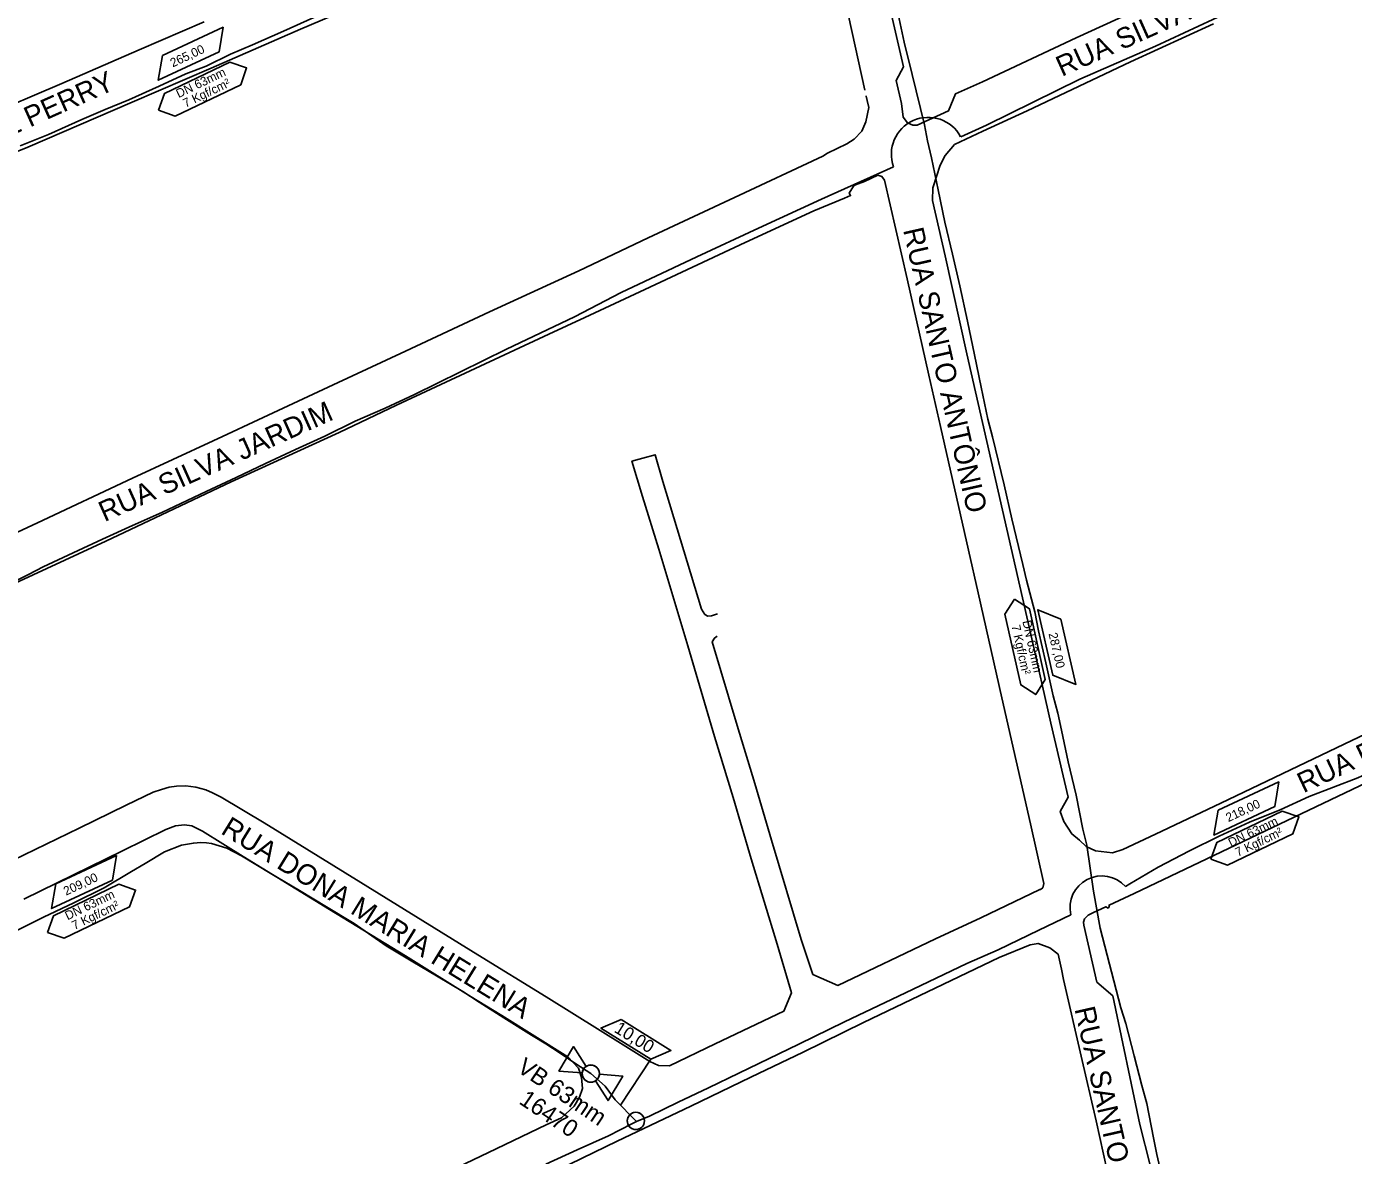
# Model space of a CAD drawing. Extents: x 656692 to 673945, y 7585994 to 7599066.
# Drawn here: x 669264.5 to 669731.5, y 7595061.7 to 7595459.1 of the extents above; entities that cross this region are included whole.
import ezdxf

# ---------------------------------------------------------------- set-up
doc = ezdxf.new("R2010")
doc.units = 0
for name, color, linetype in [('LOGRADOURO', 7, 'Continuous'), ('LOGRADOURO_TEXTO', 7, 'Continuous'), ('SIMBOLO', 7, 'Continuous'), ('TEXTO', 7, 'Continuous'), ('TUBO_PEAD_GN_63', 7, 'Continuous'), ('VALVULA_PEAD_63', 7, 'Continuous')]:
    doc.layers.add(name, color=color, linetype=linetype)

# ---------------------------------------------------------------- blocks, each defined once
blk = doc.blocks.new('VALVULA_PEAD_DN_16')
at = {"layer": 'VALVULA_PEAD_63'}
for points in [[(-0.0374, 0.0187), (-0.1395, 0.0698), (-0.1395, -0.0698), (-0.0374, -0.0187)], [(-0.0374, -0.0187), (-0.1395, -0.0698), (-0.1395, 0.0698), (-0.0374, 0.0187)], [(0.0374, -0.0187), (0.1395, -0.0698), (0.1395, 0.0698), (0.0374, 0.0187)], [(0.0374, -0.0187), (0.1395, -0.0698), (0.1395, 0.0698), (0.0374, 0.0187)]]:
    blk.add_lwpolyline(points, dxfattribs=at)
blk.add_circle((0, 0), 0.0419, dxfattribs=at)
for start, end in [(90, 270), (153.43495, 206.56505), (270, 90), (333.43495, 26.56505)]:
    blk.add_arc((0, 0), 0.0419, start, end, dxfattribs=at)
blk = doc.blocks.new('INTERLIGACAO_9')
at = {"layer": 'SIMBOLO'}
blk.add_circle((0, 0), 4.19, dxfattribs=at)
for start, end in [(0, 180), (180, 0)]:
    blk.add_arc((0, 0), 4.19, start, end, dxfattribs=at)

msp = doc.modelspace()

# ---------------------------------------------------------------- linework, layer by layer
at = {"layer": 'LOGRADOURO'}
for points in [[(669547.97, 7595489.11), (669559.52, 7595436.63)], [(669048.62, 7595307.85), (669048.61, 7595312.37), (669049.48, 7595317.48), (669051.65, 7595321.37), (669054.37, 7595324.45), (669057.28, 7595326.68), (669061.15, 7595328.65), (669091.88, 7595341.82), (669120.69, 7595354.48), (669151.36, 7595367.53), (669173.62, 7595377.26), (669235.76, 7595404.08), (669259.41, 7595414.39), (669264.95, 7595416.65), (669301.66, 7595432.47), (669329.46, 7595444.44), (669360.9, 7595458.11), (669386.36, 7595469.04)], [(669666.46, 7595470.15), (669633.85, 7595455.06), (669600.92, 7595439.57), (669591.39, 7595435.42), (669589, 7595429.36), (669577.94, 7595424.41), (669576.42, 7595424.39), (669574.49, 7595425.14), (669573, 7595427.21), (669572.36, 7595431.99), (669570.58, 7595440.07), (669573.09, 7595444.9), (669568.9, 7595463.16)], [(669326.95, 7595460.72), (669304.07, 7595450.85), (669276.93, 7595439.08), (669248.79, 7595427.06)], [(669748.41, 7595216.11), (669728.17, 7595206.43), (669684.73, 7595185.72), (669661.84, 7595174.77), (669650.34, 7595169.36), (669646.69, 7595168.25), (669640.69, 7595168.88), (669637.39, 7595170.43), (669635.05, 7595172.67), (669632.34, 7595174.86), (669629.5, 7595179.19), (669628.26, 7595182.77), (669631.06, 7595187.81), (669624.93, 7595213.87), (669618.02, 7595244.61), (669602.44, 7595313.05), (669595.44, 7595343.85), (669587.82, 7595378.35), (669583.3, 7595397.86), (669583.48, 7595402.27), (669585.99, 7595410.3), (669587.8, 7595413.7), (669591.08, 7595417.59), (669600.97, 7595422.24), (669616.61, 7595429.46), (669652.94, 7595446.6), (669682.16, 7595460.01)], [(669559.96, 7595434.64), (669559.97, 7595434.6), (669560.27, 7595433.09), (669560.89, 7595430.57), (669559.83, 7595425.52), (669558.45, 7595422.27), (669555.76, 7595419.4), (669553.14, 7595417.75), (669546.42, 7595414.56), (669544.74, 7595413.41), (669513.63, 7595398.87), (669483.22, 7595384.7), (669458.8, 7595373.13), (669427.46, 7595358.6), (669397.89, 7595344.84), (669372.44, 7595332.96), (669346.03, 7595320.67), (669333.43, 7595314.77), (669330.17, 7595313.25), (669301.77, 7595300.1), (669268.34, 7595284.32), (669236.07, 7595269.37)], [(669257.18, 7595261.61), (669292.43, 7595277.9), (669312.03, 7595287.21), (669336.48, 7595298.76), (669374.51, 7595316.23), (669394.73, 7595325.8), (669448.24, 7595350.74), (669460.93, 7595356.71), (669482.08, 7595366.55), (669517.35, 7595383.07), (669541.6, 7595394.24), (669552.38, 7595398.64), (669554.5, 7595399.56), (669554.01, 7595400.4), (669555.56, 7595402.89), (669556.19, 7595403.4), (669559.33, 7595404.55), (669564.04, 7595406.8), (669565.49, 7595406.3), (669566.4, 7595405.02), (669574.36, 7595370.21), (669582.04, 7595336.3), (669586.15, 7595318.29), (669595.99, 7595274.71), (669599.4, 7595259.75), (669607.75, 7595222.78), (669617.84, 7595178.45), (669622.52, 7595157.43), (669622.09, 7595155.91), (669621.29, 7595155.32), (669621.11, 7595155.26), (669600.27, 7595145.35), (669584.42, 7595137.88), (669550.01, 7595121.52), (669541.22, 7595125.41), (669537.12, 7595137.75), (669526.67, 7595172.67), (669520.75, 7595192.61), (669514.59, 7595212.98), (669505.79, 7595242.49), (669506.57, 7595243.82), (669507.57, 7595244.52)], [(669507.61, 7595252.33), (669505.51, 7595251.65), (669504.27, 7595251.54), (669503.24, 7595252.14), (669502.03, 7595253.97), (669488.46, 7595298.97), (669485.7, 7595308.33), (669481.4, 7595307.14), (669477.53, 7595306.04), (669481.24, 7595293.59), (669486.96, 7595275.06), (669497.18, 7595241.12), (669506.65, 7595209.22), (669513.13, 7595187.71), (669519.54, 7595166.09), (669528.62, 7595136.08), (669533.67, 7595118.9), (669531.04, 7595112.5), (669506.79, 7595100.93), (669490.79, 7595093.25), (669486.85, 7595093.4), (669483.86, 7595094.75), (669475.39, 7595100.04), (669447.32, 7595117.48), (669423.3, 7595132.36), (669382.14, 7595157.76), (669348.08, 7595178.79), (669333, 7595187.84), (669329.9, 7595189.36), (669327.56, 7595190.4), (669324.07, 7595191.33), (669320.49, 7595191.75), (669317.25, 7595191.72), (669314.63, 7595191.32), (669311.93, 7595190.55), (669309.03, 7595189.56), (669299.52, 7595184.96), (669283.01, 7595176.92), (669236.42, 7595154.36)], [(669838.43, 7595241.73), (669654.33, 7595153.92), (669645.47, 7595149.83), (669645.47, 7595149.15), (669645.1, 7595148.74), (669644.29, 7595149.26), (669639.99, 7595147.17), (669638.12, 7595146.28), (669636.81, 7595144.94), (669636.51, 7595143.86), (669636.53, 7595142.72), (669641.18, 7595122.69), (669646.8, 7595117.84), (669656.29, 7595072.57), (669663.57, 7595043.93)], [(669263.53, 7595151.91), (669298.24, 7595168.94), (669313.48, 7595176.38), (669316.95, 7595177.67), (669320.04, 7595178.05), (669322.66, 7595177.75), (669326.47, 7595175.78), (669340.71, 7595166.95), (669371.09, 7595148.26), (669397.81, 7595131.9), (669420.97, 7595117.57), (669431.73, 7595110.94), (669455, 7595096.4), (669458.71, 7595092.42), (669459.79, 7595089.14), (669460.13, 7595085.26), (669459.06, 7595082.23), (669457.17, 7595079.06), (669452.78, 7595074.98), (669447.32, 7595072.42), (669427.03, 7595062.73), (669400.04, 7595049.85)], [(669447.53, 7595054.67), (669472.33, 7595066.7), (669498.29, 7595079), (669519.37, 7595089.27), (669537.79, 7595098.09), (669558.99, 7595108.43), (669606.72, 7595131.34), (669617.73, 7595135.86), (669620.46, 7595136.33), (669624.6, 7595134.8), (669627.51, 7595132.51), (669628.67, 7595127.23), (669629.41, 7595123.63), (669635.61, 7595096.64), (669640.93, 7595073.88), (669646.03, 7595050.36)]]:
    msp.add_lwpolyline(points, dxfattribs=at)
at = {"layer": 'SIMBOLO'}
for points in [[(669310.94, 7595429.6), (669313.01, 7595435.51), (669336.03, 7595446.56), (669341.93, 7595444.49), (669339.86, 7595438.59), (669316.84, 7595427.53), (669310.94, 7595429.6)], [(669612.17, 7595257.51), (669617.45, 7595254.15), (669622.99, 7595229.22), (669619.63, 7595223.94), (669614.35, 7595227.3), (669608.81, 7595252.23), (669612.17, 7595257.51)], [(669681.25, 7595165.94), (669683.32, 7595171.84), (669706.34, 7595182.9), (669712.24, 7595180.83), (669710.17, 7595174.92), (669687.15, 7595163.86), (669681.25, 7595165.94)], [(669271.85, 7595140.19), (669273.93, 7595146.09), (669296.94, 7595157.15), (669302.85, 7595155.08), (669300.78, 7595149.18), (669277.76, 7595138.12), (669271.85, 7595140.19)]]:
    msp.add_lwpolyline(points, dxfattribs=at)
at = {"layer": 'TEXTO'}
msp.add_line((669473.49, 7595079.41), (669484.21, 7595095.58), dxfattribs=at)
for points in [[(669312.39, 7595448.85), (669333.68, 7595458.82), (669332.26, 7595450.17), (669310.85, 7595440.15), (669312.39, 7595448.85)], [(669312.39, 7595448.86), (669333.68, 7595458.82), (669332.27, 7595450.17), (669310.85, 7595440.15), (669312.39, 7595448.86)], [(669628.52, 7595250.43), (669633.78, 7595227.52), (669625.62, 7595230.72), (669620.33, 7595253.77), (669628.52, 7595250.43)], [(669683.87, 7595183.18), (669705.16, 7595193.15), (669703.75, 7595184.5), (669682.33, 7595174.47), (669683.87, 7595183.18)], [(669274.84, 7595157.29), (669296.12, 7595167.26), (669294.71, 7595158.61), (669273.29, 7595148.58), (669274.84, 7595157.29)], [(669274.84, 7595157.29), (669296.12, 7595167.26), (669294.71, 7595158.61), (669273.29, 7595148.59), (669274.84, 7595157.29)], [(669473.73, 7595109.54), (669491.23, 7595098.68), (669484.21, 7595095.58), (669466.6, 7595106.5), (669473.73, 7595109.54)]]:
    msp.add_lwpolyline(points, dxfattribs=at)
at = {"layer": 'TUBO_PEAD_GN_63'}
for points in [[(669593.23, 7595420.27), (669602.37, 7595424.36), (669635.18, 7595440.51), (669661.79, 7595452.21), (669712.19, 7595475.76), (669749.78, 7595494.45), (669772.18, 7595503.71)], [(669262.25, 7595417.09), (669272.2, 7595421.13), (669283.96, 7595426.3), (669292.18, 7595429.82), (669300.47, 7595433.29), (669311.17, 7595438.1), (669320.55, 7595442.42), (669327.69, 7595445.18), (669336.29, 7595449.37), (669344.04, 7595452.67), (669354.95, 7595457.47), (669365.61, 7595462.23)], [(669571.25, 7595463.49), (669573.34, 7595453.61), (669576.13, 7595442.14), (669580.45, 7595424.46), (669581.53, 7595418.89), (669583.01, 7595412.89), (669585.36, 7595401.62), (669587.63, 7595390.19), (669590.36, 7595378.97), (669592.94, 7595367.85), (669595.63, 7595355.41), (669598.11, 7595343.57), (669600.49, 7595332.1), (669602.83, 7595320.82), (669604.46, 7595314.68), (669608.52, 7595297.75), (669611.21, 7595285.79), (669615.16, 7595269.71), (669616.41, 7595264.22), (669619.3, 7595253.01), (669620.66, 7595246.31), (669623.16, 7595235.09), (669625.78, 7595223.49), (669627.38, 7595217.34), (669628.7, 7595211.41), (669631.1, 7595200.25), (669633.84, 7595188.5), (669636.19, 7595176.54), (669637.62, 7595170.96), (669639.97, 7595154.71), (669642.36, 7595141.68), (669649.54, 7595113.69), (669651.31, 7595108.19), (669654.31, 7595096.78), (669656.98, 7595086.26), (669658.71, 7595079.97), (669661.11, 7595067.85), (669662.3, 7595062.03), (669665.01, 7595050.25)], [(669253.26, 7595260.31), (669265.22, 7595266.2), (669270.36, 7595268.92), (669280.89, 7595273.77), (669291.18, 7595278.57), (669301.77, 7595283.39), (669312.13, 7595288.04), (669327.75, 7595295.44), (669338.23, 7595300.32), (669348.63, 7595305.22), (669359.19, 7595310.19), (669369.46, 7595314.89), (669380.1, 7595320.11), (669390.73, 7595324.69), (669400.99, 7595329.54), (669433.34, 7595345.52), (669457.35, 7595356.9), (669473.72, 7595365.46), (669500.37, 7595378.06), (669522.08, 7595388.1), (669544.22, 7595398.33), (669569.63, 7595409.7)], [(669651.19, 7595156.38), (669652.77, 7595157.35), (669662.73, 7595163.12), (669673.73, 7595168.87), (669684.25, 7595174.12), (669694.82, 7595178.96), (669705.67, 7595183.31), (669715.82, 7595188.05), (669733.03, 7595194.66), (669743.71, 7595199.55), (669754.07, 7595204.78), (669764.71, 7595210.45), (669775.42, 7595215.98), (669790.56, 7595223.91), (669802.13, 7595229.73), (669814.3, 7595236.08), (669839.51, 7595247.78), (669849.68, 7595252.43), (669869.56, 7595261.57), (669875.3, 7595267.62)], [(669260.13, 7595140.38), (669270.45, 7595145.59), (669281.18, 7595150.59), (669291.84, 7595155.9), (669301.48, 7595161.63), (669306.23, 7595164.46), (669313.06, 7595168.6), (669318.99, 7595170.89), (669323.2, 7595171.65), (669325.78, 7595171.8), (669327.83, 7595171.68), (669329.57, 7595171.47), (669335.01, 7595169.82), (669340.14, 7595167.11), (669350.18, 7595161.09), (669360.53, 7595154.93), (669370.08, 7595149.23), (669379.75, 7595143.33), (669391.1, 7595135.46), (669400.38, 7595129.8), (669408.74, 7595124.87), (669418, 7595119.36), (669423.76, 7595115.7), (669432.47, 7595110.16), (669442.24, 7595104.04), (669447.28, 7595101.02), (669452.33, 7595097.67), (669457.79, 7595093.92), (669463.07, 7595090.5), (669468.16, 7595086.08), (669471.66, 7595081.29), (669479.11, 7595073.66)], [(669447.19, 7595058.67), (669458.25, 7595063.67), (669469.24, 7595068.62), (669477.52, 7595072.77), (669479.11, 7595073.66), (669483.75, 7595075.47), (669493.85, 7595080.46), (669504.47, 7595085.49), (669515.19, 7595090.64), (669536.24, 7595100.85), (669552.37, 7595108.77), (669573.8, 7595118.97), (669595.39, 7595129.22), (669606.37, 7595134.07), (669620.77, 7595141.04), (669631.96, 7595146.42)]]:
    msp.add_lwpolyline(points, dxfattribs=at)
for centre, radius, start, end in [((669581.8, 7595414.15), 12.96, 28.163, 200.072), ((669642.88, 7595148.89), 11.19, 42.0578, 192.7242)]:
    msp.add_arc(centre, radius, start, end, dxfattribs=at)

# ---------------------------------------------------------------- block references
at = {"layer": 'SIMBOLO', "xscale": 0.7229249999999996, "yscale": 0.7229249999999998, "rotation": 166.312122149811}
msp.add_blockref('INTERLIGACAO_9', (669478.93, 7595073.84), dxfattribs=at)
at = {"layer": 'VALVULA_PEAD_63', "xscale": 72.29249999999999, "yscale": 72.29249999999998, "rotation": -30.993872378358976}
msp.add_blockref('VALVULA_PEAD_DN_16', (669463.07, 7595090.5), dxfattribs=at)

# ---------------------------------------------------------------- texts
for s, p in [('VB 63mm', (669436.73, 7595091.49)), ('16470', (669437.46, 7595080.16))]:
    msp.add_text(s, height=6, rotation=326.048).set_placement(p)
at = {"layer": 'LOGRADOURO_TEXTO'}
for s, rotation, p in [('RUA SILVA JARDIM', 24.1047, (669628.82, 7595441.33)), ('RUA LUIZ PERRY', 24.1047, (669223.17, 7595404.51)), ('RUA SANTO ANTÔNIO', 282.7896, (669572.93, 7595387.49)), ('RUA SILVA JARDIM', 24.1047, (669291.92, 7595284.61)), ('RUA BENJAMIN CONSTANT', 25.3644, (669713.85, 7595189.13)), ('RUA DONA MARIA HELENA', 328.3795, (669332.5, 7595175.19)), ('RUA SANTO ANTÔNIO', 282.7896, (669633.25, 7595113.27))]:
    msp.add_text(s, height=7.2, rotation=rotation, dxfattribs=at).set_placement(p)
at = {"layer": 'TEXTO'}
for s, height, rotation, p in [('265,00', 3.113, 25.0891, (669315.94, 7595444.66)), ('DN 63mm', 3.113, 25.66, (669318.02, 7595433.86)), ('7 Kgf/cm²', 3.113, 25.66, (669320.46, 7595430.46)), ('7 Kgf/cm²', 3.113, 282.5179, (669611.06, 7595248.1)), ('DN 63mm', 3.113, 282.5179, (669614.93, 7595249.71)), ('287,00', 3.113, 282.9405, (669624.12, 7595245.36)), ('218,00', 3.113, 25.0891, (669687.43, 7595178.99)), ('DN 63mm', 3.113, 25.66, (669688.33, 7595170.2)), ('7 Kgf/cm²', 3.113, 25.66, (669690.77, 7595166.79)), ('209,00', 3.113, 25.0891, (669278.39, 7595153.1)), ('DN 63mm', 3.113, 25.66, (669278.93, 7595144.45)), ('7 Kgf/cm²', 3.113, 25.66, (669281.37, 7595141.04)), ('10,00', 4.447, 328.1976, (669470.96, 7595105.34))]:
    msp.add_text(s, height=height, rotation=rotation, dxfattribs=at).set_placement(p)

doc.saveas('drawing.dxf')
